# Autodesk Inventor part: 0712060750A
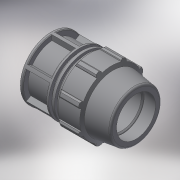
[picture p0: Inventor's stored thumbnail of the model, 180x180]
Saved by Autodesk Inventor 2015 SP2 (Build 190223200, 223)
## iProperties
Created: 2017-02
Part Number: 0712060750A
Material: Generic
Description: PLASSON END PLUG 75
Document SubType Name: Modeling
Designer: KIM
Mass: 947.017 g
Surface Area: 1382.98 cm^2
Volume: 947.017 cm^3
Density: 1 g/cm^3
Appearance: Default
Author: Кирилл
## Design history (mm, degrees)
derived "87120.ipt"
feature "Solid1::87120.ipt"
tag "TaggingFeature1"
body "Solid1"
other parameters: "d2" = 75, "d4" = 24.57143, "d5" = 43, "d7" = 134, "d8" = 100.5, "d9" = 24.57143, "d11" = 4.91429, "d12" = 107.2, "d13" = 120 deg, "d14" = 97.5, "d15" = 8 deg, "d16" = 120.6, "d18" = 3.75, "d19" = 35 deg, "d20" = 17.5 deg, "d21" = 124.62, "d23" = 0, "d25" = 360 deg, "d27" = 2.68, "d34" = 6.7, "d36" = 0, "d42" = 43, "d43" = 4.02, "d46" = 2.25, "d53" = 1.5, "d55" = 360 deg, "d59" = 43, "d64" = 172, "d66" = 17.42, "d67" = 10.72, "d68" = 155, "d70" = 19.65714, "d71" = 4.91429, "d72" = 118.188, "d75" = 9.82857, "d_" = 75, "E_" = 134, "H_" = 172, "l_" = 155
